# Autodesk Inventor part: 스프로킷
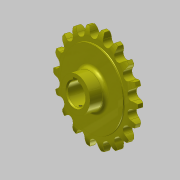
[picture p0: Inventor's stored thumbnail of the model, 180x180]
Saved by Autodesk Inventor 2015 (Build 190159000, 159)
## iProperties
Created: 2016-03
Part Number: 스프로킷
Material: 강철, 탄소
Document SubType Name: Modeling
Designer: mduedu
Density: 7.87 g/cm^3
Mass: 300.014 g
Surface Area: 127.848 cm^2
Volume: 38.1212 cm^3
Appearance: 노란색
Author: mduedu
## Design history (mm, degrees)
sketch "스케치1"
  geometry: L1 (0, 5)-(29.5, 5); L2 (29.5, 5)-(29.5, 4.1); L3 (30, 3.6)-(33.625, 3.6); L4 (40, 2)-(40, 0); L5 (40, 0)-(0, 0); L6 (0, 0)-(0, 5); L7 (0, -5)-(29.5, -5); L8 (29.5, -5)-(29.5, -4.1); L9 (30, -3.6)-(33.625, -3.6); L10 (40, -2)-(40, 0); L11 (0, 0)-(0, -5); A1 r 13.5 centre (33.625, -9.9) between (40, 2) and (33.625, 3.6); A2 r 13.5 centre (33.625, 9.9) between (33.625, -3.6) and (40, -2); A3 r 0.5 centre (30, 4.1) between (29.5, 4.1) and (30, 3.6); A4 r 0.5 centre (30, -4.1) between (30, -3.6) and (29.5, -4.1); 2 further points
  constraints: 22 end point, 8 point on circle, 6 symmetric about line, 5 tangent, 4 centre point, 4 parallel, 4 point on line, 1 equal radius, 1 horizontal, 1 perpendicular, 1 other
  dimensions: "d0" = 80 diameter of L4 L6; "d2" = 59 diameter of L2 L6; "d3" = 1.6 vertical distance of L4.start L3.end; "d4" = 3.6 distance from line of L4.end L3; "d5" = 5 distance between parallel lines of L5 L1; "d6" = 13.5 radius of A1; "d15" = 0.5 radius of A3
revolve "회전1" sketch "스케치1" stored, may be unused: angle "d7" = 90 deg
sketch "스케치2" dims "d8" = 65.2, "d11" = 80
  geometry: L1 (0, 0)-(0, 32.6); A1 r 36.57 centre (0, 0) between (-16.231, 32.771) and (0, 36.57); A2 r 3.97 centre (0, 36.57) between (-3.866, 35.665) and (0, 32.6); A3 r 12.7 centre (-16.231, 32.771) between (-3.866, 35.665) and (-5.534, 39.615); A4 r 12.7 centre (16.231, 32.771) between (5.534, 39.615) and (3.866, 35.665); A5 r 3.97 centre (0, 36.57) between (0, 32.6) and (3.866, 35.665); A6 r 40 centre (0, 0) between (5.534, 39.615) and (-5.534, 39.615); 2 further points
  constraints: 12 point on circle, 6 centre point, 4 coincident, 3 symmetric about line, 2 end point, 1 point on line, 1 tangent, 1 vertical, 1 vertical alignment, 7 other
  dimensions: "d10" = 73.14 diameter of A1; "d12" = 12.7 radius of A3
extrude "돌출1" cut sketch "스케치2" stored distance "d13" = 10; taper "d14" = 0 deg
sketch "스케치3"
  geometry: C1 r 13.5 at (0, 0); 1 further point
  constraints: 1 centre point, 1 coincident
  dimensions: "d19" = 27 diameter of C1
extrude "돌출2" join sketch "스케치3" distance "d20" = 13; taper "d21" = 0 deg
fillet "모깎기1" dims "d22" = 3
sketch "스케치4"
  geometry: L1 (-2.5, 0)-(2.5, 0); L2 (2.5, 0)-(2.5, 10.8); L3 (2.5, 10.8)-(-2.5, 10.8); L4 (-2.5, 10.8)-(-2.5, 0); C1 r 8.5 at (0, 0); 2 further points
  constraints: 8 end point, 2 coincident, 2 parallel, 1 centre point, 1 horizontal, 1 midpoint, 1 perpendicular
  dimensions: "d23" = 17 diameter of C1; "d25" = 5 distance of L2.end L3.end; "d26" = 10.8 distance of L1.end L2.end
extrude "돌출3" cut sketch "스케치4" stored distance "d27" = 8; taper "d28" = 0 deg
chamfer "모따기1" distance "d29" = 1; stored, may be unused: second distance "d30" = 2, angle "d31" = 45 deg
node "작업 평면1"
sketch "스케치5"
  geometry: L1 (13.5, 13)-(-13.5, 13) reference; 2 further points
  constraints: 1 vertical alignment
  dimensions: "d32" = 4 distance from line of point (0, 9) L1
hole "구멍1" sketch "스케치5" at (0, 9) diameter "d33" = 2.459; stored, may be unused: countersink angle "d37" = 90 deg, drill point angle "d39" = 118 deg; dims "d34" = 6, "d35" = 4, "d36" = 2, "d38" = 8
node "솔리드1"
pattern_circular "원형 패턴1" dims angle "d17" = 360 deg
